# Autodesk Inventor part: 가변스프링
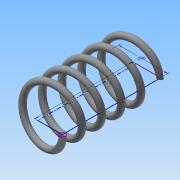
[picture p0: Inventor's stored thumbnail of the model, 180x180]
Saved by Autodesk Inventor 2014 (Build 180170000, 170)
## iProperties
Created: 2018-04
Part Number: 가변스프링
Material: 일반
Document SubType Name: Modeling
Designer: net
Density: 1 g/cm^3
Appearance: 기본값
Mass: 12.1639 g
Surface Area: 98.7896 cm^2
Volume: 12.1639 cm^3
Author: net
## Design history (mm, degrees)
sketch "스케치1"
  geometry: L1 (0, 0)-(20, 0); L2 (20, 0)-(20, 75.25); L3 (20, 75.25)-(0, 75.25); L4 (0, 75.25)-(0, 0); C1 r 2.5 at (20, 0)
  constraints: 8 end point, 2 parallel, 1 centre point, 1 coincident, 1 horizontal, 1 perpendicular
  dimensions: "d0" = 75.25 distance of L3.end L1.start (derived); "d1" = 40 diameter of L2 L4
feature "코일1" sketch "스케치1" pitch "d4" = 10; turns "d6" = 5; dims "d5" = 75.25 (= d0), "d7" = 0, angle "d8" = 90 deg, angle "d9" = 90 deg, "d10" = 0, "d11" = 0
node "작업 평면1"
sketch "스케치2"
  geometry: L1 (-17.5, 0)-(-22.5, 0) reference; 1 further point
  constraints: 1 horizontal alignment
extrude "돌출1" cut sketch "스케치2" distance "d12" = 27.25; taper "d13" = 0 deg
node "작업 평면2"
sketch "스케치3"
  geometry: L1 (17.5, 0)-(22.5, 0) reference; 1 further point
  constraints: 1 horizontal alignment
extrude "돌출2" cut sketch "스케치3" distance "d14" = 27.25; taper "d15" = 0 deg
node "솔리드1"
node "절단 모서리 투영1"
node "절단 모서리 투영2"
